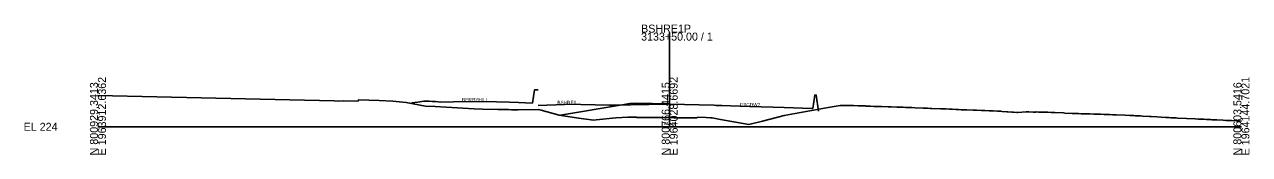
# Model space of a CAD drawing. Extents: x -26 to 403, y -10 to 6039.
# Drawn here: x -25.7 to 402.8, y 4990.3 to 5035.8 of the extents above; entities that cross this region are included whole.
import ezdxf

# ---------------------------------------------------------------- set-up
doc = ezdxf.new("R2010")
doc.units = 0
for name, color, linetype in [('Default', 7, 'Continuous'), ('RD_GPK_XS_Cell', 7, 'Continuous'), ('RD_TX_Misc1', 7, 'Continuous'), ('RD_XS_ExGround', 7, 'Continuous'), ('RD_XS_Pave', 7, 'Continuous'), ('RD_XS_TX_Elev_EX', 7, 'Continuous')]:
    doc.layers.add(name, color=color, linetype=linetype)

msp = doc.modelspace()

# ---------------------------------------------------------------- linework, layer by layer
at = {"layer": 'Default'}
msp.add_line((20.58, 5010.53), (82.59, 5009.07), dxfattribs=at)
at = {"layer": 'RD_GPK_XS_Cell'}
for p, q in [((200, 5000), (200, 5032.98)), ((0, 5000), (200, 5000)), ((200, 5000), (400, 5000))]:
    msp.add_line(p, q, dxfattribs=at)
at = {"layer": 'RD_XS_ExGround'}
for points in [[(0, 5010.99), (20.58, 5010.53)], [(82.59, 5009.07), (84.31, 5009.02), (85.89, 5009.14), (91.05, 5009.01), (91.17, 5009.46), (98.32, 5009.22), (103.13, 5009.03), (107.77, 5008.51), (114.62, 5007.28), (117.92, 5007.12), (121.85, 5006.92), (131.63, 5006.33), (134.48, 5006.21), (139.84, 5006.11), (143.59, 5006.04), (144.62, 5005.98), (145.3, 5005.97), (147.05, 5005.98), (154.12, 5006.06), (155.1, 5005.87), (161.38, 5004.08), (168.13, 5003.06), (173.42, 5002.3), (174.25, 5002.4), (181.18, 5003.15), (185.32, 5003.33), (185.84, 5003.34), (188.02, 5003.4), (188.42, 5003.37), (188.43, 5003.32), (189.1, 5003.29), (190.51, 5003.28), (191.12, 5003.27), (193.56, 5003.25), (195.46, 5003.23), (196.59, 5003.22), (197.14, 5003.21), (198.99, 5003.2), (200, 5003.21), (201.47, 5003.19), (202.68, 5003.18), (204.07, 5003.17), (205.05, 5003.16), (205.77, 5003.15), (206.85, 5003.14), (208.31, 5003.12), (208.62, 5003.12), (209.62, 5003.1), (209.67, 5003.22), (209.67, 5003.35), (212.73, 5003.21), (214.3, 5003.12), (214.83, 5003.12), (217.75, 5002.6), (227.65, 5000.82), (232.49, 5002.03), (240.07, 5003.98), (255.43, 5006.75), (259.65, 5007.51), (262.03, 5007.49), (264.29, 5007.44), (265.99, 5007.38), (267.25, 5007.33), (268.38, 5007.29), (268.78, 5007.27), (270.23, 5007.21), (271.43, 5007.17), (273.43, 5007.11), (274.09, 5007.09), (276.42, 5007.01), (276.86, 5006.99), (277.43, 5006.97), (279.51, 5006.9), (280.35, 5006.86), (281.74, 5006.83), (282.54, 5006.81), (284.76, 5006.73), (285.92, 5006.69), (288.66, 5006.57), (290.16, 5006.49), (291.12, 5006.45), (291.74, 5006.43), (294.75, 5006.31), (296.57, 5006.24), (297.85, 5006.19), (298.79, 5006.15), (300.09, 5006.09), (301.01, 5006.05), (301.97, 5006), (303.12, 5005.94), (304.01, 5005.9), (306.2, 5005.82), (307.04, 5005.79), (307.39, 5005.78), (309.03, 5005.72), (310.2, 5005.67), (311.76, 5005.6), (313.17, 5005.55), (314.65, 5005.49), (315.8, 5005.44), (316.34, 5005.4), (318, 5005.24), (318.3, 5005.22), (319.7, 5005.14), (320.3, 5005.1), (321.44, 5005.06), (321.77, 5005.04), (324.66, 5005.28), (325.28, 5005.23), (325.67, 5005.21), (327.14, 5005.15), (327.94, 5005.12), (328.25, 5005.19), (329.06, 5005.18), (330.45, 5005.17), (331.66, 5005.11), (332.34, 5005.08), (333.43, 5005.03), (334.72, 5004.98), (337.78, 5004.85), (338.26, 5004.83), (340.77, 5004.71), (341.79, 5004.67), (343.06, 5004.62), (343.93, 5004.6), (346.22, 5004.54), (346.94, 5004.51), (348.41, 5004.46), (350.32, 5004.4), (350.68, 5004.39), (352.03, 5004.34), (353.13, 5004.29), (353.87, 5004.26), (354.99, 5004.22), (355.73, 5004.19), (356.22, 5004.17), (359.27, 5004.05), (360.98, 5003.97), (362.35, 5003.91), (362.82, 5003.89), (363.53, 5003.86), (364.68, 5003.81), (365.42, 5003.76), (367.87, 5003.61), (368.48, 5003.58), (370.38, 5003.48), (371.94, 5003.39), (373.53, 5003.3), (374.6, 5003.24), (375.36, 5003.2), (376.49, 5003.13), (377.19, 5003.09), (377.67, 5003.06), (380.83, 5002.9), (383.82, 5002.76), (384.88, 5002.72), (386.89, 5002.63), (387.83, 5002.59), (389.2, 5002.52), (389.65, 5002.5), (389.96, 5002.48), (391.47, 5002.4), (393.62, 5002.31), (394.58, 5002.26), (396.56, 5002.17), (398.15, 5002.1), (398.77, 5002.07), (399.21, 5002.04), (400, 5002)]]:
    msp.add_lwpolyline(points, dxfattribs=at)
at = {"layer": 'RD_XS_Pave'}
for points in [[(109.84, 5008.34), (111.91, 5008.68), (113.95, 5009.02), (115.89, 5008.96), (116.95, 5008.92), (118.03, 5008.82), (119.96, 5008.62), (124.33, 5008.71), (131.97, 5008.86), (139.46, 5008.71), (143.98, 5008.62), (147.07, 5008.5), (151.99, 5008.3), (152.74, 5012.97), (153.23, 5012.97), (154, 5012.97)], [(161.82, 5004.1), (183.44, 5007.73), (186.02, 5008.16), (188.01, 5008.32), (199.66, 5007.99), (200, 5007.98), (200, 5007.98), (215.56, 5007.53), (216.28, 5007.51), (218.28, 5007.45), (221.33, 5007.36), (228, 5007.17), (240.02, 5006.82), (249.7, 5006.45), (250.03, 5006.44), (250.78, 5011.11), (251.28, 5011.11), (252.04, 5005.44)], [(153.95, 5007.49), (163.2, 5007.87), (163.95, 5007.9), (179, 5007.62), (179.97, 5007.6), (199.08, 5007.98), (200, 5007.99), (200, 5007.99)]]:
    msp.add_lwpolyline(points, dxfattribs=at)

# ---------------------------------------------------------------- texts
at = {"layer": 'Default'}
msp.add_text('-', height=0.0001, dxfattribs=at).set_placement((0, 5000))
at = {"layer": 'RD_GPK_XS_Cell'}
for s, p in [('BSHRE1P', (190, 5032.98)), ('3133+50.00 / 1', (190, 5030.18)), ('EL 224', (-26, 4998.6))]:
    msp.add_text(s, height=2.8, dxfattribs=at).set_placement(p)
for s, p in [('N 800929.3413', (0, 4990)), ('E 1963912.6362', (2.8, 4990)), ('N 800766.4415', (200, 4990)), ('E 1964028.6692', (202.8, 4990)), ('N 800603.5416', (400, 4990)), ('E 1964144.7021', (402.8, 4990))]:
    msp.add_text(s, height=2.8, rotation=90, dxfattribs=at).set_placement(p)
at = {"layer": 'RD_TX_Misc1'}
for s, p in [('BERRYHILL', (127.39, 5008.92)), ('BSHRE0', (160.71, 5007.9)), ('I20CDW2', (224.51, 5007.17))]:
    msp.add_text(s, height=1.2, dxfattribs=at).set_placement(p)
at = {"layer": 'RD_XS_TX_Elev_EX'}
msp.add_text('227.21', height=1, dxfattribs=at).set_placement((197.99, 5000.71))

doc.saveas('drawing.dxf')
